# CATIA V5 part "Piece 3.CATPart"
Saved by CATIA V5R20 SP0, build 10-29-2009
Part number: Piece 3
Bounding box of the stored display mesh (mm): x 0 to 10, y 258.115 to 591.999, z -20.413 to 11.996
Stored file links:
  C:\Users\Lambert\Desktop\IAO\Piece 3.CATPart
  C:\Users\Lambert\Desktop\IAO\Ass_Mon_IAO.CATProduct
  C:\Users\Lambert\Desktop\IAO\skl_general.CATPart
  C:\Users\Lambert\Desktop\IAO\Piece3.CATPart
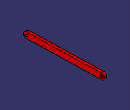
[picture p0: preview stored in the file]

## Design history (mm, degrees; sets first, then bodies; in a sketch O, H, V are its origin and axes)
Set1
  DatumPoint1 "F": linked copy from another document
  Point1 "G": linked copy from another document
Body1 (main body)
  Sketch1 on yz-plane, origin (0, 0, 0), H (0, 1, 0), V (0, 0, 1)
    construction line L1 (580, 0) -> (270.1143, -8.4178)
    point P1 (580, 0)
    point P2 (270.1143, -8.4178)
    line L2 (580.3258, -11.9956) -> (270.4402, -20.4133)
    line L3 (269.7885, 3.5778) -> (579.6742, 11.9956)
    arc A1 centre (270.1143, -8.4178) radius 12 from (270.4402, -20.4133) to (269.7885, 3.5778) cw
    arc A2 centre (580, 0) radius 12 from (579.6742, 11.9956) to (580.3258, -11.9956) cw
    reference projected point E1 (270.1143, -8.4178) from DatumPoint1
    reference projected point E2 (580, 0) from Point1
    distance L1 L2 = 12
    tangency: A1 L2, A2 L2, A1 L3, A2 L3
    coincidence: P2 E1, P1 E2
  Pad1: profile Sketch1, direction (1, 0, 0), length 10
  Sketch2 on end face of Pad1, origin (10, 382.1117, -13.6671), H (0, 1, 0), V (0, 0, 1)
    point P1 (-111.9974, 5.2493)
    reference projected point E1 (-111.9974, 5.2493) from DatumPoint1
    coincidence: P1 E1
  Hole1: placed by Sketch2, at (10, 270.1143, -8.4178) direction (-1, 0, 0), diameter 10, depth 10
  Sketch3 on end face of Pad1, origin (10, 531.5917, 4.3773), H (0, 1, 0), V (0, 0, 1)
    point P1 (48.4083, -4.3773)
    reference projected point E1 (48.4083, -4.3773) from Point1
    coincidence: P1 E1
  Hole2: placed by Sketch3, at (10, 580, 0) direction (-1, 0, 0), diameter 10, depth 10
